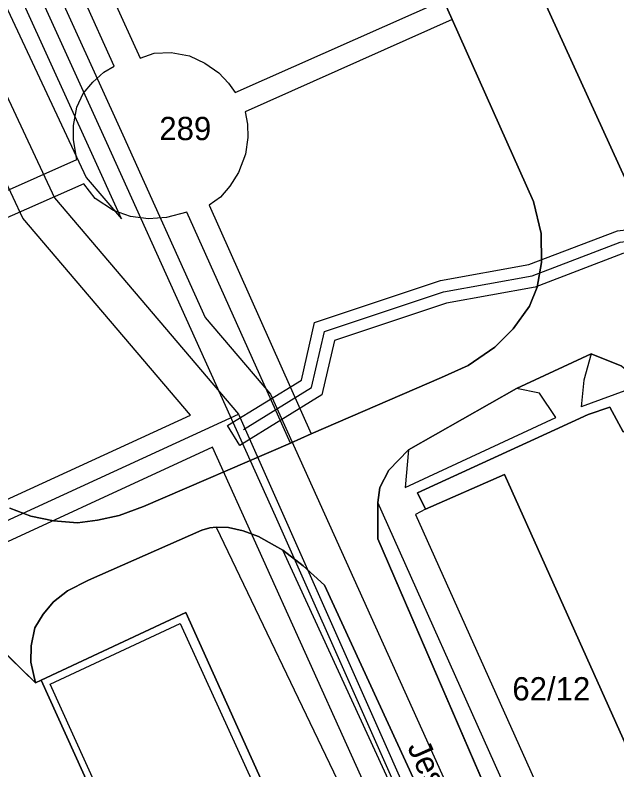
# Model space of a CAD drawing. Extents: x -264070 to -262271, y -1238894 to -1238141.
# Drawn here: x -263429.8 to -263378.1, y -1238782.8 to -1238718 of the extents above; entities that cross this region are included whole.
import ezdxf

# ---------------------------------------------------------------- set-up
doc = ezdxf.new("R2010")
doc.units = 0
for name, color, linetype in [('body_kn', 7, 'Continuous'), ('kladpar_druhypozemkov', 7, 'Continuous'), ('kladpar_hranice', 7, 'Continuous'), ('kladpar_parcelnecisla', 7, 'Continuous'), ('kladpar_plochy', 7, 'Continuous'), ('popisy', 7, 'Continuous'), ('tarchy_linie', 7, 'Continuous'), ('zappar_hrandruhpozemk', 7, 'Continuous')]:
    doc.layers.add(name, color=color, linetype=linetype)

msp = doc.modelspace()

# ---------------------------------------------------------------- linework, layer by layer
at = {"layer": 'body_kn'}
for p, q in [((-263392.24, -1238718.36), (-263392.24, -1238718.36)), ((-263392.24, -1238718.36), (-263392.24, -1238718.36)), ((-263417.84, -1238721.26), (-263417.84, -1238721.26)), ((-263416.37, -1238721.18), (-263416.37, -1238721.18)), ((-263419.04, -1238721.68), (-263419.04, -1238721.68)), ((-263414.79, -1238721.48), (-263414.79, -1238721.48)), ((-263413.5, -1238722.11), (-263413.5, -1238722.11)), ((-263421.29, -1238722.38), (-263421.29, -1238722.38)), ((-263422.16, -1238722.89), (-263422.16, -1238722.89)), ((-263412.27, -1238722.95), (-263412.27, -1238722.95)), ((-263423.12, -1238723.73), (-263423.12, -1238723.73)), ((-263411.46, -1238723.82), (-263411.46, -1238723.82)), ((-263410.87, -1238724.64), (-263410.87, -1238724.64)), ((-263423.93, -1238724.72), (-263423.93, -1238724.72)), ((-263424.48, -1238725.88), (-263424.48, -1238725.88)), ((-263410.03, -1238726.3), (-263410.03, -1238726.3)), ((-263424.78, -1238727.47), (-263424.78, -1238727.47)), ((-263409.82, -1238727.34), (-263409.82, -1238727.34)), ((-263420.54, -1238728.27), (-263420.54, -1238728.27)), ((-263409.8, -1238728.48), (-263409.8, -1238728.48)), ((-263424.78, -1238728.7), (-263424.78, -1238728.7)), ((-263421.94, -1238728.91), (-263421.94, -1238728.91)), ((-263423.34, -1238729.55), (-263423.34, -1238729.55)), ((-263424.49, -1238730.38), (-263424.49, -1238730.38)), ((-263409.98, -1238729.92), (-263409.98, -1238729.92)), ((-263410.58, -1238731.51), (-263410.58, -1238731.51)), ((-263423.89, -1238732.48), (-263423.89, -1238732.48)), ((-263423.68, -1238731.93), (-263423.68, -1238731.93)), ((-263411.33, -1238732.68), (-263411.33, -1238732.68)), ((-263426.4, -1238733.67), (-263426.4, -1238733.67)), ((-263422.91, -1238733.74), (-263422.91, -1238733.74)), ((-263412.15, -1238733.63), (-263412.15, -1238733.63)), ((-263413.11, -1238734.29), (-263413.11, -1238734.29)), ((-263385.25, -1238733.98), (-263385.25, -1238733.98)), ((-263421.32, -1238734.76), (-263421.32, -1238734.76)), ((-263415.03, -1238734.9), (-263415.03, -1238734.9)), ((-263429.12, -1238735.41), (-263429.12, -1238735.41)), ((-263420.66, -1238735.48), (-263420.66, -1238735.48)), ((-263419.88, -1238735.27), (-263419.88, -1238735.27)), ((-263418.32, -1238735.49), (-263418.32, -1238735.49)), ((-263416.77, -1238735.37), (-263416.77, -1238735.37)), ((-263384.6, -1238736.74), (-263384.6, -1238736.74)), ((-263385.64, -1238739.41), (-263385.64, -1238739.41)), ((-263384.55, -1238739.23), (-263384.55, -1238739.23)), ((-263393.23, -1238740.77), (-263393.23, -1238740.77)), ((-263385.37, -1238740.38), (-263385.37, -1238740.38)), ((-263385.1, -1238741.35), (-263385.1, -1238741.35)), ((-263384.94, -1238741.36), (-263384.94, -1238741.36)), ((-263392.98, -1238741.74), (-263392.98, -1238741.74)), ((-263392.73, -1238742.71), (-263392.73, -1238742.71)), ((-263385.6, -1238742.97), (-263385.6, -1238742.97)), ((-263413.46, -1238743.94), (-263413.46, -1238743.94)), ((-263404.05, -1238744.38), (-263404.05, -1238744.38)), ((-263403.2, -1238745.15), (-263403.2, -1238745.15)), ((-263386.99, -1238744.92), (-263386.99, -1238744.92)), ((-263402.35, -1238745.92), (-263402.35, -1238745.92)), ((-263388.58, -1238746.5), (-263388.58, -1238746.5)), ((-263380.29, -1238747.07), (-263380.29, -1238747.07)), ((-263380.29, -1238747.07), (-263380.29, -1238747.07)), ((-263390.86, -1238748.06), (-263390.86, -1238748.06)), ((-263405.19, -1238749.33), (-263405.19, -1238749.33)), ((-263393.14, -1238749.1), (-263393.14, -1238749.1)), ((-263380.91, -1238749.33), (-263380.91, -1238749.33)), ((-263404.31, -1238749.96), (-263404.31, -1238749.96)), ((-263407.84, -1238750.54), (-263407.84, -1238750.54)), ((-263403.43, -1238750.59), (-263403.43, -1238750.59)), ((-263386.7, -1238750.04), (-263386.7, -1238750.04)), ((-263384.73, -1238750.46), (-263384.73, -1238750.46)), ((-263381.14, -1238751.63), (-263381.14, -1238751.63)), ((-263378.69, -1238751.65), (-263378.69, -1238751.65)), ((-263414.71, -1238752.34), (-263414.71, -1238752.34)), ((-263410.58, -1238752.26), (-263410.58, -1238752.26)), ((-263383.34, -1238752.54), (-263383.34, -1238752.54)), ((-263383.34, -1238752.54), (-263383.34, -1238752.54)), ((-263380.56, -1238752.29), (-263380.56, -1238752.29)), ((-263411.54, -1238753.24), (-263411.54, -1238753.24)), ((-263410.16, -1238753.57), (-263410.16, -1238753.57)), ((-263383.41, -1238753.6), (-263383.41, -1238753.6)), ((-263404.35, -1238753.95), (-263404.35, -1238753.95)), ((-263412.82, -1238755.1), (-263412.82, -1238755.1)), ((-263410.49, -1238754.95), (-263410.49, -1238754.95)), ((-263406.14, -1238754.73), (-263406.14, -1238754.73)), ((-263406.14, -1238754.73), (-263406.14, -1238754.73)), ((-263396, -1238755.32), (-263396, -1238755.32)), ((-263396, -1238755.32), (-263396, -1238755.32)), ((-263397.67, -1238757.07), (-263397.67, -1238757.07)), ((-263387.74, -1238757.44), (-263387.74, -1238757.44)), ((-263398.46, -1238758.54), (-263398.46, -1238758.54)), ((-263396.28, -1238758.54), (-263396.28, -1238758.54)), ((-263395.22, -1238759.02), (-263395.22, -1238759.02)), ((-263418.76, -1238760.19), (-263418.76, -1238760.19)), ((-263398.63, -1238759.83), (-263398.63, -1238759.83)), ((-263428.44, -1238761.01), (-263428.44, -1238761.01)), ((-263420.86, -1238760.97), (-263420.86, -1238760.97)), ((-263407.44, -1238760.98), (-263407.44, -1238760.98)), ((-263395.39, -1238760.86), (-263395.39, -1238760.86)), ((-263395.39, -1238760.86), (-263395.39, -1238760.86)), ((-263394.53, -1238760.42), (-263394.53, -1238760.42)), ((-263394.53, -1238760.42), (-263394.53, -1238760.42)), ((-263426.49, -1238761.4), (-263426.49, -1238761.4)), ((-263424.43, -1238761.59), (-263424.43, -1238761.59)), ((-263422.72, -1238761.35), (-263422.72, -1238761.35)), ((-263413.74, -1238762.22), (-263413.74, -1238762.22)), ((-263413.05, -1238762.01), (-263413.05, -1238762.01)), ((-263412.51, -1238761.95), (-263412.51, -1238761.95)), ((-263412.51, -1238761.95), (-263412.51, -1238761.95)), ((-263411.46, -1238761.99), (-263411.46, -1238761.99)), ((-263410.2, -1238762.26), (-263410.2, -1238762.26)), ((-263408.88, -1238762.77), (-263408.88, -1238762.77)), ((-263398.61, -1238762.95), (-263398.61, -1238762.95)), ((-263407.51, -1238763.52), (-263407.51, -1238763.52)), ((-263406.79, -1238763.94), (-263406.79, -1238763.94)), ((-263405.05, -1238765.27), (-263405.05, -1238765.27)), ((-263423.49, -1238766.52), (-263423.49, -1238766.52)), ((-263425.29, -1238767.44), (-263425.29, -1238767.44)), ((-263403.2, -1238766.95), (-263403.2, -1238766.95)), ((-263426.49, -1238768.37), (-263426.49, -1238768.37)), ((-263427.39, -1238769.44), (-263427.39, -1238769.44)), ((-263415.13, -1238769.29), (-263415.13, -1238769.29)), ((-263415.13, -1238769.29), (-263415.13, -1238769.29)), ((-263428.08, -1238770.61), (-263428.08, -1238770.61)), ((-263415.61, -1238770.22), (-263415.61, -1238770.22)), ((-263428.42, -1238772.14), (-263428.42, -1238772.14)), ((-263428.45, -1238773.55), (-263428.45, -1238773.55)), ((-263427.56, -1238775.1), (-263427.56, -1238775.1)), ((-263428.03, -1238775.32), (-263428.03, -1238775.32)), ((-263426.77, -1238775.44), (-263426.77, -1238775.44)), ((-263426.77, -1238775.44), (-263426.77, -1238775.44))]:
    msp.add_line(p, q, dxfattribs=at)
at = {"layer": 'kladpar_druhypozemkov'}
for p, q in [((-263414.89, -1238726.7), (-263414.89, -1238726.7)), ((-263383.8, -1238774.8), (-263383.8, -1238774.8))]:
    msp.add_line(p, q, dxfattribs=at)
at = {"layer": 'kladpar_hranice'}
for points in [[(-263375.37, -1238705.86), (-263374.29, -1238705.48), (-263373.16, -1238708.15), (-263374.13, -1238708.64), (-263365.15, -1238728.6), (-263376.65, -1238733.6), (-263385.78, -1238713.56), (-263388.36, -1238714.73), (-263389.52, -1238712.06), (-263386.98, -1238710.93), (-263387.63, -1238709.51), (-263396.16, -1238690.79), (-263397.2, -1238688.5), (-263389.76, -1238685.11), (-263388.78, -1238687.26), (-263384.63, -1238685.28), (-263375.37, -1238705.86)], [(-263385.78, -1238713.56), (-263376.65, -1238733.6)], [(-263392.98, -1238716.7), (-263392.24, -1238718.36), (-263385.25, -1238733.98), (-263384.6, -1238736.74), (-263384.55, -1238739.23), (-263384.94, -1238741.36), (-263385.6, -1238742.97), (-263386.99, -1238744.92), (-263388.58, -1238746.5), (-263390.86, -1238748.06), (-263393.14, -1238749.1), (-263404.35, -1238753.95), (-263406.14, -1238754.73), (-263418.76, -1238760.19), (-263420.86, -1238760.97), (-263422.72, -1238761.35), (-263424.43, -1238761.59), (-263426.49, -1238761.4), (-263428.44, -1238761.01), (-263430.24, -1238760.32)], [(-263430.24, -1238760.32), (-263428.44, -1238761.01), (-263426.49, -1238761.4), (-263424.43, -1238761.59), (-263422.72, -1238761.35), (-263420.86, -1238760.97), (-263418.76, -1238760.19), (-263406.14, -1238754.73), (-263404.35, -1238753.95), (-263393.14, -1238749.1), (-263390.86, -1238748.06), (-263388.58, -1238746.5), (-263386.99, -1238744.92), (-263385.6, -1238742.97), (-263384.94, -1238741.36), (-263384.55, -1238739.23), (-263384.6, -1238736.74), (-263385.25, -1238733.98), (-263392.24, -1238718.36), (-263392.98, -1238716.7)], [(-263382.17, -1238800.97), (-263398.61, -1238762.95), (-263398.63, -1238759.83), (-263398.46, -1238758.54), (-263397.67, -1238757.07), (-263396, -1238755.32), (-263386.7, -1238750.04), (-263380.29, -1238747.07), (-263377.65, -1238748.14), (-263375.82, -1238749.66), (-263375.57, -1238751.23), (-263375.49, -1238752.18), (-263375.44, -1238752.84), (-263377.54, -1238753.78), (-263378.69, -1238751.65), (-263380.56, -1238752.29), (-263383.41, -1238753.6), (-263395.22, -1238759.02), (-263394.53, -1238760.42), (-263387.74, -1238757.44), (-263371.12, -1238794.41)], [(-263377.65, -1238748.14), (-263380.29, -1238747.07), (-263386.7, -1238750.04), (-263396, -1238755.32), (-263397.67, -1238757.07), (-263398.46, -1238758.54), (-263398.63, -1238759.83), (-263398.61, -1238762.95), (-263382.17, -1238800.97)], [(-263368.82, -1238764.58), (-263368.59, -1238765.1), (-263367.57, -1238767.47), (-263367.52, -1238767.58), (-263366.7, -1238769.47), (-263359.69, -1238784.36), (-263357.29, -1238783.39), (-263356.15, -1238786.03), (-263358.48, -1238787.03), (-263357.83, -1238788.47), (-263362.28, -1238790.41), (-263365.56, -1238791.93), (-263371.12, -1238794.41), (-263387.74, -1238757.44), (-263394.53, -1238760.42), (-263395.22, -1238759.02), (-263383.41, -1238753.6), (-263380.56, -1238752.29), (-263378.69, -1238751.65), (-263377.54, -1238753.78), (-263375.44, -1238752.84), (-263374.56, -1238752.44), (-263374.16, -1238752.26), (-263368.82, -1238764.58)], [(-263379.82, -1238817.71), (-263403.2, -1238766.95), (-263405.05, -1238765.27), (-263406.79, -1238763.94), (-263407.51, -1238763.52), (-263408.88, -1238762.77), (-263410.2, -1238762.26), (-263411.46, -1238761.99), (-263412.51, -1238761.95), (-263413.05, -1238762.01), (-263413.74, -1238762.22), (-263423.49, -1238766.52), (-263425.29, -1238767.44), (-263426.49, -1238768.37), (-263427.39, -1238769.44), (-263428.08, -1238770.61), (-263428.42, -1238772.14), (-263428.45, -1238773.55), (-263428.03, -1238775.32), (-263439.22, -1238764.47)], [(-263405.97, -1238789.56), (-263415.13, -1238769.29), (-263427.56, -1238775.1), (-263428.03, -1238775.32), (-263428.45, -1238773.55), (-263428.42, -1238772.14), (-263428.08, -1238770.61), (-263427.39, -1238769.44), (-263426.49, -1238768.37), (-263425.29, -1238767.44), (-263423.49, -1238766.52), (-263413.74, -1238762.22), (-263413.05, -1238762.01), (-263412.51, -1238761.95), (-263411.46, -1238761.99), (-263410.2, -1238762.26), (-263408.88, -1238762.77), (-263407.51, -1238763.52), (-263406.79, -1238763.94), (-263405.05, -1238765.27), (-263403.2, -1238766.95), (-263379.82, -1238817.71)], [(-263439.22, -1238764.47), (-263428.03, -1238775.32), (-263427.56, -1238775.1), (-263407.58, -1238819.17)], [(-263415.13, -1238769.29), (-263405.97, -1238789.56), (-263405.79, -1238789.48), (-263405.43, -1238790.27), (-263404.64, -1238792.02), (-263404.37, -1238792.62), (-263404.55, -1238792.7), (-263395.24, -1238813.3), (-263407.58, -1238819.17), (-263427.56, -1238775.1), (-263415.13, -1238769.29)]]:
    msp.add_lwpolyline(points, dxfattribs=at)
at = {"layer": 'kladpar_plochy'}
for p, q in [((-263385.78, -1238713.56), (-263376.65, -1238733.6)), ((-263392.24, -1238718.36), (-263392.98, -1238716.7)), ((-263385.25, -1238733.98), (-263392.24, -1238718.36)), ((-263384.6, -1238736.74), (-263385.25, -1238733.98)), ((-263384.55, -1238739.23), (-263384.6, -1238736.74)), ((-263384.94, -1238741.36), (-263384.55, -1238739.23)), ((-263385.6, -1238742.97), (-263384.94, -1238741.36)), ((-263386.99, -1238744.92), (-263385.6, -1238742.97)), ((-263388.58, -1238746.5), (-263386.99, -1238744.92)), ((-263390.86, -1238748.06), (-263388.58, -1238746.5)), ((-263380.29, -1238747.07), (-263386.7, -1238750.04)), ((-263377.65, -1238748.14), (-263380.29, -1238747.07)), ((-263393.14, -1238749.1), (-263390.86, -1238748.06)), ((-263404.35, -1238753.95), (-263393.14, -1238749.1)), ((-263386.7, -1238750.04), (-263396, -1238755.32)), ((-263406.14, -1238754.73), (-263404.35, -1238753.95)), ((-263418.76, -1238760.19), (-263406.14, -1238754.73)), ((-263396, -1238755.32), (-263397.67, -1238757.07)), ((-263397.67, -1238757.07), (-263398.46, -1238758.54)), ((-263398.46, -1238758.54), (-263398.63, -1238759.83)), ((-263430.24, -1238760.32), (-263428.44, -1238761.01)), ((-263420.86, -1238760.97), (-263418.76, -1238760.19)), ((-263398.63, -1238759.83), (-263398.61, -1238762.95)), ((-263428.44, -1238761.01), (-263426.49, -1238761.4)), ((-263422.72, -1238761.35), (-263420.86, -1238760.97)), ((-263426.49, -1238761.4), (-263424.43, -1238761.59)), ((-263424.43, -1238761.59), (-263422.72, -1238761.35)), ((-263413.74, -1238762.22), (-263423.49, -1238766.52)), ((-263413.05, -1238762.01), (-263413.74, -1238762.22)), ((-263412.51, -1238761.95), (-263413.05, -1238762.01)), ((-263411.46, -1238761.99), (-263412.51, -1238761.95)), ((-263410.2, -1238762.26), (-263411.46, -1238761.99)), ((-263408.88, -1238762.77), (-263410.2, -1238762.26)), ((-263407.51, -1238763.52), (-263408.88, -1238762.77)), ((-263398.61, -1238762.95), (-263382.17, -1238800.97)), ((-263406.79, -1238763.94), (-263407.51, -1238763.52)), ((-263405.05, -1238765.27), (-263406.79, -1238763.94)), ((-263428.03, -1238775.32), (-263439.22, -1238764.47)), ((-263439.22, -1238764.47), (-263428.03, -1238775.32)), ((-263403.2, -1238766.95), (-263405.05, -1238765.27)), ((-263423.49, -1238766.52), (-263425.29, -1238767.44)), ((-263425.29, -1238767.44), (-263426.49, -1238768.37)), ((-263379.82, -1238817.71), (-263403.2, -1238766.95)), ((-263426.49, -1238768.37), (-263427.39, -1238769.44)), ((-263427.39, -1238769.44), (-263428.08, -1238770.61)), ((-263428.08, -1238770.61), (-263428.42, -1238772.14)), ((-263428.42, -1238772.14), (-263428.45, -1238773.55)), ((-263428.45, -1238773.55), (-263428.03, -1238775.32)), ((-263428.03, -1238775.32), (-263427.56, -1238775.1)), ((-263427.56, -1238775.1), (-263407.58, -1238819.17))]:
    msp.add_line(p, q, dxfattribs=at)
for points in [[(-263375.37, -1238705.86), (-263374.29, -1238705.48), (-263373.16, -1238708.15), (-263374.13, -1238708.64), (-263365.15, -1238728.6), (-263376.65, -1238733.6), (-263385.78, -1238713.56), (-263388.36, -1238714.73), (-263389.52, -1238712.06), (-263386.98, -1238710.93), (-263387.63, -1238709.51), (-263396.16, -1238690.79), (-263397.2, -1238688.5), (-263389.76, -1238685.11), (-263388.78, -1238687.26), (-263384.63, -1238685.28)], [(-263368.82, -1238764.58), (-263368.59, -1238765.1), (-263367.57, -1238767.47), (-263367.52, -1238767.58), (-263366.7, -1238769.47), (-263359.69, -1238784.36), (-263357.29, -1238783.39), (-263356.15, -1238786.03), (-263358.48, -1238787.03), (-263357.83, -1238788.47), (-263362.28, -1238790.41), (-263365.56, -1238791.93), (-263371.12, -1238794.41), (-263387.74, -1238757.44), (-263394.53, -1238760.42), (-263395.22, -1238759.02), (-263383.41, -1238753.6), (-263380.56, -1238752.29), (-263378.69, -1238751.65), (-263377.54, -1238753.78), (-263375.44, -1238752.84), (-263374.56, -1238752.44), (-263374.16, -1238752.26)], [(-263415.13, -1238769.29), (-263405.97, -1238789.56), (-263405.79, -1238789.48), (-263405.43, -1238790.27), (-263404.64, -1238792.02), (-263404.37, -1238792.62), (-263404.55, -1238792.7), (-263395.24, -1238813.3), (-263407.58, -1238819.17), (-263427.56, -1238775.1)]]:
    msp.add_lwpolyline(points, close=True, dxfattribs=at)
for points in [[(-263392.98, -1238716.7), (-263392.24, -1238718.36), (-263385.25, -1238733.98), (-263384.6, -1238736.74), (-263384.55, -1238739.23), (-263384.94, -1238741.36), (-263385.6, -1238742.97), (-263386.99, -1238744.92), (-263388.58, -1238746.5), (-263390.86, -1238748.06), (-263393.14, -1238749.1), (-263404.35, -1238753.95), (-263406.14, -1238754.73), (-263418.76, -1238760.19), (-263420.86, -1238760.97), (-263422.72, -1238761.35), (-263424.43, -1238761.59), (-263426.49, -1238761.4), (-263428.44, -1238761.01), (-263430.24, -1238760.32)], [(-263382.17, -1238800.97), (-263398.61, -1238762.95), (-263398.63, -1238759.83), (-263398.46, -1238758.54), (-263397.67, -1238757.07), (-263396, -1238755.32), (-263386.7, -1238750.04), (-263380.29, -1238747.07), (-263377.65, -1238748.14), (-263375.82, -1238749.66), (-263375.57, -1238751.23), (-263375.49, -1238752.18), (-263375.44, -1238752.84), (-263377.54, -1238753.78), (-263378.69, -1238751.65), (-263380.56, -1238752.29), (-263383.41, -1238753.6), (-263395.22, -1238759.02), (-263394.53, -1238760.42), (-263387.74, -1238757.44), (-263371.12, -1238794.41)], [(-263405.97, -1238789.56), (-263415.13, -1238769.29), (-263427.56, -1238775.1), (-263428.03, -1238775.32), (-263428.45, -1238773.55), (-263428.42, -1238772.14), (-263428.08, -1238770.61), (-263427.39, -1238769.44), (-263426.49, -1238768.37), (-263425.29, -1238767.44), (-263423.49, -1238766.52), (-263413.74, -1238762.22), (-263413.05, -1238762.01), (-263412.51, -1238761.95), (-263411.46, -1238761.99), (-263410.2, -1238762.26), (-263408.88, -1238762.77), (-263407.51, -1238763.52), (-263406.79, -1238763.94), (-263405.05, -1238765.27), (-263403.2, -1238766.95), (-263379.82, -1238817.71)]]:
    msp.add_lwpolyline(points, dxfattribs=at)
at = {"layer": 'tarchy_linie'}
for points in [[(-263441.6, -1238708.78), (-263438.67, -1238707.5), (-263435.73, -1238706.21), (-263423.68, -1238731.93), (-263420.66, -1238735.48), (-263423.34, -1238729.55), (-263434.27, -1238705.57), (-263432.86, -1238704.96), (-263431.45, -1238704.34), (-263420.54, -1238728.27), (-263413.46, -1238743.94), (-263407.84, -1238750.54), (-263375.09, -1238823.12)], [(-263432.86, -1238704.96), (-263421.94, -1238728.91), (-263407.44, -1238760.98), (-263382.73, -1238816.54), (-263370.12, -1238846.22)], [(-263438.67, -1238707.5), (-263426.4, -1238733.67), (-263410.58, -1238752.26), (-263393, -1238791.83), (-263378.04, -1238824.37), (-263372.7, -1238837.95), (-263367.93, -1238845.22)], [(-263380.99, -1238825.62), (-263412.82, -1238755.1), (-263435.69, -1238765.61), (-263454.43, -1238773.05), (-263455.64, -1238769.98), (-263448.46, -1238767.13), (-263447.87, -1238768.43), (-263439.22, -1238764.47), (-263439.6, -1238763.61), (-263436.99, -1238762.57), (-263414.71, -1238752.34), (-263429.12, -1238735.41), (-263441.6, -1238708.78)], [(-263356.96, -1238741.2), (-263364.64, -1238736.93), (-263377.56, -1238738.46), (-263385.1, -1238741.35), (-263392.73, -1238742.71), (-263402.35, -1238745.92), (-263403.43, -1238750.59), (-263410.49, -1238754.95), (-263411.54, -1238753.24), (-263405.19, -1238749.33), (-263404.05, -1238744.38), (-263393.23, -1238740.77), (-263385.64, -1238739.41), (-263378.04, -1238736.5), (-263364.24, -1238734.87), (-263354.69, -1238740.18), (-263356.19, -1238740.85), (-263356.96, -1238741.2)], [(-263410.16, -1238753.57), (-263404.31, -1238749.96), (-263403.2, -1238745.15), (-263392.98, -1238741.74), (-263385.37, -1238740.38), (-263377.8, -1238737.48), (-263364.44, -1238735.9), (-263356.51, -1238740.31), (-263356.19, -1238740.85)], [(-263453.64, -1238770.96), (-263436.34, -1238764.09), (-263410.58, -1238752.26)]]:
    msp.add_lwpolyline(points, dxfattribs=at)
at = {"layer": 'zappar_hrandruhpozemk'}
for p, q in [((-263427.72, -1238702.72), (-263419.04, -1238721.68)), ((-263421.29, -1238722.38), (-263429.69, -1238703.57)), ((-263410.87, -1238724.64), (-263392.98, -1238716.7)), ((-263392.24, -1238718.36), (-263410.03, -1238726.3)), ((-263442.46, -1238738.34), (-263424.49, -1238730.38)), ((-263423.89, -1238732.48), (-263441.58, -1238740.26)), ((-263413.11, -1238734.29), (-263404.35, -1238753.95)), ((-263406.14, -1238754.73), (-263415.03, -1238734.9)), ((-263375.82, -1238749.66), (-263381.14, -1238751.63)), ((-263396.28, -1238758.54), (-263383.34, -1238752.54)), ((-263396, -1238755.32), (-263396.28, -1238758.54)), ((-263380.52, -1238800.3), (-263398.63, -1238759.83)), ((-263394.53, -1238760.42), (-263395.39, -1238760.86)), ((-263395.39, -1238760.86), (-263378.12, -1238799.3)), ((-263412.51, -1238761.95), (-263400.13, -1238787.75)), ((-263396.59, -1238786.06), (-263406.79, -1238763.94)), ((-263407.42, -1238818.25), (-263426.77, -1238775.44))]:
    msp.add_line(p, q, dxfattribs=at)
for points in [[(-263419.04, -1238721.68), (-263417.84, -1238721.26), (-263416.37, -1238721.18), (-263414.79, -1238721.48), (-263413.5, -1238722.11), (-263412.27, -1238722.95), (-263411.46, -1238723.82), (-263410.87, -1238724.64)], [(-263424.49, -1238730.38), (-263424.78, -1238728.7), (-263424.78, -1238727.47), (-263424.48, -1238725.88), (-263423.93, -1238724.72), (-263423.12, -1238723.73), (-263422.16, -1238722.89), (-263421.29, -1238722.38)], [(-263410.03, -1238726.3), (-263409.82, -1238727.34), (-263409.8, -1238728.48), (-263409.98, -1238729.92), (-263410.58, -1238731.51), (-263411.33, -1238732.68), (-263412.15, -1238733.63), (-263413.11, -1238734.29)], [(-263415.03, -1238734.9), (-263416.77, -1238735.37), (-263418.32, -1238735.49), (-263419.88, -1238735.27), (-263421.32, -1238734.76), (-263422.91, -1238733.74), (-263423.89, -1238732.48)], [(-263380.29, -1238747.07), (-263380.91, -1238749.33), (-263381.14, -1238751.63)], [(-263383.34, -1238752.54), (-263384.73, -1238750.46), (-263386.7, -1238750.04)], [(-263426.77, -1238775.44), (-263415.61, -1238770.22), (-263406.65, -1238789.87)]]:
    msp.add_lwpolyline(points, dxfattribs=at)

# ---------------------------------------------------------------- texts
at = {"layer": 'kladpar_parcelnecisla'}
for s, p in [('289', (-263417.397, -1238728.72)), ('62/12', (-263387.063, -1238776.84))]:
    msp.add_text(s, height=2, dxfattribs=at).set_placement(p)
at = {"layer": 'popisy'}
msp.add_text('Jesenná', height=2, rotation=294, dxfattribs=at).set_placement((-263396.122, -1238780.829))

doc.saveas('drawing.dxf')
